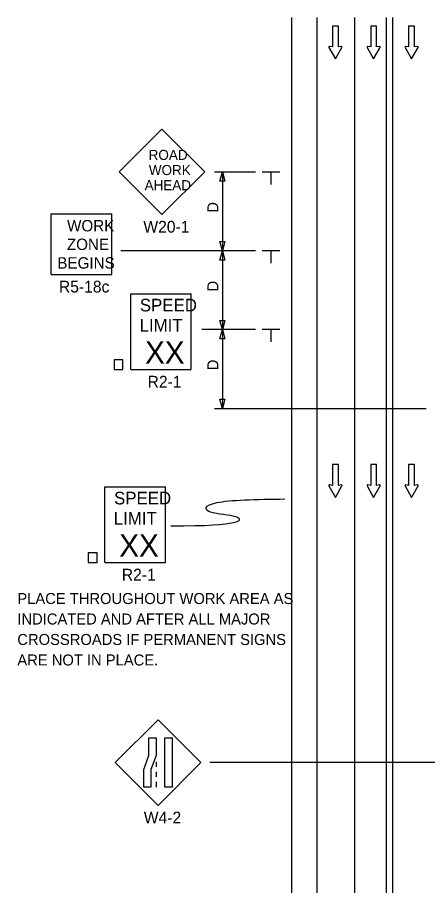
# Model space of a CAD drawing. Extents: x 16733 to 18475, y 7003 to 8205.
# Drawn here: x 16737 to 16998, y 7640 to 8191 of the extents above; entities that cross this region are included whole.
import ezdxf

# ---------------------------------------------------------------- set-up
doc = ezdxf.new("R2010")
doc.units = 0
for name, color, linetype in [('ALI_LEGAL_EX', 7, 'Continuous'), ('MT_SCRATCH_LEVEL_E', 7, 'Continuous'), ('PAVT_EDGE_EX', 7, 'Continuous'), ('TRAFFIC_SIGNS_PR', 7, 'Continuous'), ('TYPICAL_TEXT_DIMEN_PR', 7, 'Continuous')]:
    doc.layers.add(name, color=color, linetype=linetype)

msp = doc.modelspace()

# ---------------------------------------------------------------- linework, layer by layer
at = {"layer": 'ALI_LEGAL_EX'}
for p, q in [((16951.37, 8191.42), (16951.37, 7362.23)), ((16971.37, 8191.42), (16971.37, 7362.23)), ((16975.37, 8191.42), (16975.37, 7362.23))]:
    msp.add_line(p, q, dxfattribs=at)
for points in [[(16951.37, 8191.42), (16951.37, 8166.42)], [(16975.37, 8191.42), (16975.37, 8166.42)], [(16951.37, 8091.42), (16951.37, 8066.42)], [(16975.37, 8091.42), (16975.37, 8066.42)], [(16951.37, 7991.42), (16951.37, 7966.42)], [(16975.37, 7991.42), (16975.37, 7966.42)], [(16951.37, 7891.42), (16951.37, 7866.42)], [(16975.37, 7891.42), (16975.37, 7866.42)], [(16951.37, 7791.42), (16951.37, 7766.42)], [(16975.37, 7791.42), (16975.37, 7766.42)], [(16951.37, 7691.42), (16951.37, 7666.42)], [(16975.37, 7691.42), (16975.37, 7666.42)]]:
    msp.add_lwpolyline(points, dxfattribs=at)
at = {"layer": 'MT_SCRATCH_LEVEL_E'}
for p, q in [((16941.03, 8185.91), (16937.29, 8185.91)), ((16937.29, 8185.91), (16937.29, 8172.66)), ((16941.03, 8185.91), (16937.29, 8185.91)), ((16937.29, 8185.91), (16937.29, 8172.66)), ((16941.03, 8172.66), (16941.03, 8185.91)), ((16941.03, 8172.66), (16941.03, 8185.91)), ((16965.29, 8185.91), (16961.55, 8185.91)), ((16961.55, 8185.91), (16961.55, 8172.66)), ((16965.29, 8185.91), (16961.55, 8185.91)), ((16961.55, 8185.91), (16961.55, 8172.66)), ((16965.29, 8172.66), (16965.29, 8185.91)), ((16965.29, 8172.66), (16965.29, 8185.91)), ((16989.39, 8185.91), (16985.65, 8185.91)), ((16985.65, 8185.91), (16985.65, 8172.66)), ((16989.39, 8185.91), (16985.65, 8185.91)), ((16985.65, 8185.91), (16985.65, 8172.66)), ((16989.39, 8172.66), (16989.39, 8185.91)), ((16989.39, 8172.66), (16989.39, 8185.91)), ((16935.04, 8172.29), (16939.18, 8165.05)), ((16935.04, 8172.29), (16939.18, 8165.05)), ((16937.29, 8172.66), (16935.52, 8172.97)), ((16937.29, 8172.66), (16935.52, 8172.97)), ((16939.18, 8165.05), (16943.29, 8172.29)), ((16939.18, 8165.05), (16943.29, 8172.29)), ((16942.81, 8172.97), (16941.03, 8172.66)), ((16942.81, 8172.97), (16941.03, 8172.66)), ((16959.29, 8172.29), (16963.44, 8165.05)), ((16959.29, 8172.29), (16963.44, 8165.05)), ((16961.55, 8172.66), (16959.77, 8172.97)), ((16961.55, 8172.66), (16959.77, 8172.97)), ((16963.44, 8165.05), (16967.55, 8172.29)), ((16963.44, 8165.05), (16967.55, 8172.29)), ((16967.07, 8172.97), (16965.29, 8172.66)), ((16967.07, 8172.97), (16965.29, 8172.66)), ((16983.4, 8172.29), (16987.54, 8165.05)), ((16983.4, 8172.29), (16987.54, 8165.05)), ((16985.65, 8172.66), (16983.87, 8172.97)), ((16985.65, 8172.66), (16983.87, 8172.97)), ((16987.54, 8165.05), (16991.65, 8172.29)), ((16987.54, 8165.05), (16991.65, 8172.29)), ((16991.17, 8172.97), (16989.39, 8172.66)), ((16991.17, 8172.97), (16989.39, 8172.66)), ((16941.03, 7907.66), (16937.29, 7907.66)), ((16937.29, 7907.66), (16937.29, 7894.41)), ((16941.03, 7907.66), (16937.29, 7907.66)), ((16937.29, 7907.66), (16937.29, 7894.41)), ((16941.03, 7894.41), (16941.03, 7907.66)), ((16941.03, 7894.41), (16941.03, 7907.66)), ((16965.29, 7907.66), (16961.55, 7907.66)), ((16961.55, 7907.66), (16961.55, 7894.41)), ((16965.29, 7907.66), (16961.55, 7907.66)), ((16961.55, 7907.66), (16961.55, 7894.41)), ((16965.29, 7894.41), (16965.29, 7907.66)), ((16965.29, 7894.41), (16965.29, 7907.66)), ((16989.39, 7907.66), (16985.65, 7907.66)), ((16985.65, 7907.66), (16985.65, 7894.41)), ((16989.39, 7907.66), (16985.65, 7907.66)), ((16985.65, 7907.66), (16985.65, 7894.41)), ((16989.39, 7894.41), (16989.39, 7907.66)), ((16989.39, 7894.41), (16989.39, 7907.66)), ((16935.04, 7894.04), (16939.18, 7886.8)), ((16935.04, 7894.04), (16939.18, 7886.8)), ((16937.29, 7894.41), (16935.52, 7894.72)), ((16937.29, 7894.41), (16935.52, 7894.72)), ((16939.18, 7886.8), (16943.29, 7894.04)), ((16939.18, 7886.8), (16943.29, 7894.04)), ((16942.81, 7894.72), (16941.03, 7894.41)), ((16942.81, 7894.72), (16941.03, 7894.41)), ((16959.29, 7894.04), (16963.44, 7886.8)), ((16959.29, 7894.04), (16963.44, 7886.8)), ((16961.55, 7894.41), (16959.77, 7894.72)), ((16961.55, 7894.41), (16959.77, 7894.72)), ((16963.44, 7886.8), (16967.55, 7894.04)), ((16963.44, 7886.8), (16967.55, 7894.04)), ((16967.07, 7894.72), (16965.29, 7894.41)), ((16967.07, 7894.72), (16965.29, 7894.41)), ((16983.4, 7894.04), (16987.54, 7886.8)), ((16983.4, 7894.04), (16987.54, 7886.8)), ((16985.65, 7894.41), (16983.87, 7894.72)), ((16985.65, 7894.41), (16983.87, 7894.72)), ((16987.54, 7886.8), (16991.65, 7894.04)), ((16987.54, 7886.8), (16991.65, 7894.04)), ((16991.17, 7894.72), (16989.39, 7894.41)), ((16991.17, 7894.72), (16989.39, 7894.41))]:
    msp.add_line(p, q, dxfattribs=at)
for centre, start, end in [((16935.45, 8172.51), 80.0362, 209.7731), ((16935.45, 8172.51), 80.0362, 209.7731), ((16942.89, 8172.51), 330.4248, 99.9638), ((16942.89, 8172.51), 330.4248, 99.9638), ((16959.7, 8172.51), 80.0362, 209.7731), ((16959.7, 8172.51), 80.0362, 209.7731), ((16967.14, 8172.51), 330.4248, 99.9638), ((16967.14, 8172.51), 330.4248, 99.9638), ((16983.8, 8172.51), 80.0362, 209.7731), ((16983.8, 8172.51), 80.0362, 209.7731), ((16991.25, 8172.51), 330.4248, 99.9638), ((16991.25, 8172.51), 330.4248, 99.9638), ((16935.45, 7894.26), 80.0362, 209.7731), ((16935.45, 7894.26), 80.0362, 209.7731), ((16942.89, 7894.26), 330.4248, 99.9638), ((16942.89, 7894.26), 330.4248, 99.9638), ((16959.7, 7894.26), 80.0362, 209.7731), ((16959.7, 7894.26), 80.0362, 209.7731), ((16967.14, 7894.26), 330.4248, 99.9638), ((16967.14, 7894.26), 330.4248, 99.9638), ((16983.8, 7894.26), 80.0362, 209.7731), ((16983.8, 7894.26), 80.0362, 209.7731), ((16991.25, 7894.26), 330.4248, 99.9638), ((16991.25, 7894.26), 330.4248, 99.9638)]:
    msp.add_arc(centre, 0.463, start, end, dxfattribs=at)
at = {"layer": 'PAVT_EDGE_EX'}
for p, q in [((16911.37, 8191.42), (16911.37, 7362.23)), ((16927.37, 8191.42), (16927.37, 7362.23))]:
    msp.add_line(p, q, dxfattribs=at)
at = {"layer": 'TRAFFIC_SIGNS_PR'}
for p, q in [((16829.01, 8120.55), (16801.86, 8093.4)), ((16856.17, 8093.4), (16829.01, 8120.55)), ((16801.86, 8093.4), (16829.01, 8066.24)), ((16829.01, 8066.24), (16856.17, 8093.4)), ((16758.75, 8028.23), (16758.75, 8066.63)), ((16758.75, 8066.63), (16797.15, 8066.63)), ((16797.15, 8028.23), (16797.15, 8066.63)), ((16758.75, 8028.23), (16797.15, 8028.23)), ((16809.2, 8015.93), (16847.6, 8015.93)), ((16809.2, 7967.93), (16809.2, 8015.93)), ((16847.6, 7967.93), (16847.6, 8015.93)), ((16809.2, 7967.93), (16847.6, 7967.93)), ((16792.81, 7893.45), (16831.21, 7893.45)), ((16792.81, 7845.45), (16792.81, 7893.45)), ((16831.21, 7845.45), (16831.21, 7893.45)), ((16792.81, 7845.45), (16831.21, 7845.45)), ((16826.5, 7745.61), (16799.35, 7718.45)), ((16853.65, 7718.45), (16826.5, 7745.61)), ((16799.35, 7718.45), (16826.5, 7691.3)), ((16825.25, 7718.95), (16825.25, 7715.75)), ((16826.5, 7691.3), (16853.65, 7718.45)), ((16825.25, 7712.55), (16825.25, 7709.35)), ((16825.25, 7706.15), (16825.25, 7702.95))]:
    msp.add_line(p, q, dxfattribs=at)
for points in [[(16798.59, 7967.93), (16804.18, 7967.93), (16804.18, 7974.1), (16798.59, 7974.1)], [(16782.2, 7845.45), (16787.79, 7845.45), (16787.79, 7851.62), (16782.2, 7851.62)], [(16825.25, 7734.19), (16825.25, 7723.01), (16821.91, 7714.13), (16821.91, 7702.95), (16817.42, 7702.95), (16817.42, 7714.13), (16820.76, 7723.01), (16820.76, 7734.19)], [(16835.39, 7734.19), (16835.39, 7702.95), (16830.9, 7702.95), (16830.9, 7734.19)]]:
    msp.add_lwpolyline(points, close=True, dxfattribs=at)
at = {"layer": 'TYPICAL_TEXT_DIMEN_PR'}
for p, q in [((16888.37, 8093.23), (16862.37, 8093.23)), ((16865.8, 8087.37), (16867.37, 8093.23)), ((16867.37, 8093.23), (16867.37, 8043.23)), ((16867.37, 8093.23), (16868.94, 8087.37)), ((16903.87, 8093.23), (16892.62, 8093.23)), ((16898.24, 8093.23), (16898.24, 8085.45)), ((16867.37, 8087.37), (16865.8, 8087.37)), ((16868.94, 8087.37), (16867.37, 8087.37)), ((16867.37, 8043.23), (16865.8, 8049.09)), ((16865.8, 8049.09), (16867.37, 8049.09)), ((16867.37, 8049.09), (16868.94, 8049.09)), ((16868.94, 8049.09), (16867.37, 8043.23)), ((16888.37, 8043.23), (16802.89, 8043.23)), ((16865.8, 8037.37), (16867.37, 8043.23)), ((16867.37, 8043.23), (16867.37, 7993.23)), ((16867.37, 8043.23), (16868.94, 8037.37)), ((16903.87, 8043.23), (16892.62, 8043.23)), ((16898.24, 8043.23), (16898.24, 8035.45)), ((16867.37, 8037.37), (16865.8, 8037.37)), ((16868.94, 8037.37), (16867.37, 8037.37)), ((16867.37, 7993.23), (16865.8, 7999.09)), ((16865.8, 7999.09), (16867.37, 7999.09)), ((16867.37, 7999.09), (16868.94, 7999.09)), ((16868.94, 7999.09), (16867.37, 7993.23)), ((16888.37, 7993.23), (16854.31, 7993.23)), ((16865.8, 7987.37), (16867.37, 7993.23)), ((16867.37, 7993.23), (16867.37, 7943.23)), ((16867.37, 7993.23), (16868.94, 7987.37)), ((16903.87, 7993.23), (16892.62, 7993.23)), ((16898.24, 7993.23), (16898.24, 7985.45)), ((16867.37, 7987.37), (16865.8, 7987.37)), ((16868.94, 7987.37), (16867.37, 7987.37)), ((16867.37, 7943.23), (16865.8, 7949.09)), ((16865.8, 7949.09), (16867.37, 7949.09)), ((16867.37, 7949.09), (16868.94, 7949.09)), ((16868.94, 7949.09), (16867.37, 7943.23)), ((16862.37, 7943.23), (16996.75, 7943.23)), ((16859.36, 7718.7), (17007.56, 7718.7))]:
    msp.add_line(p, q, dxfattribs=at)
msp.add_open_spline([(16834.65, 7868.68), (16880.74, 7868.68), (16880.74, 7875.95), (16855.56, 7875.95), (16855.56, 7884.63), (16888.56, 7885.63), (16907.07, 7885.77)], degree=3, dxfattribs=at)

# ---------------------------------------------------------------- texts
at = {"layer": 'TRAFFIC_SIGNS_PR'}
for s, height, p in [('ROAD', 6.4, (16820.56, 8100.93)), ('WORK', 6.4, (16820.67, 8091.33)), ('AHEAD', 6.4, (16817.98, 8081.73)), ('WORK', 7.217, (16768.75, 8055.59)), ('W20-1', 7.44, (16817.18, 8054.81)), ('ZONE', 7.217, (16768.63, 8043.78)), ('BEGINS', 7.217, (16762.56, 8031.97)), ('R5-18c', 7.44, (16763.56, 8016.79)), ('SPEED', 8, (16814.96, 8004.79)), ('LIMIT', 8, (16814.8, 7991.99)), ('XX', 14.031, (16818.31, 7971.69)), ('R2-1', 7.44, (16819.87, 7956.49)), ('SPEED', 8, (16798.57, 7882.32)), ('LIMIT', 8, (16798.41, 7869.52)), ('XX', 14.031, (16801.92, 7849.21)), ('R2-1', 7.44, (16803.48, 7834.01)), ('PLACE THROUGHOUT WORK AREA AS', 7, (16737.17, 7819.08)), ('INDICATED AND AFTER ALL MAJOR', 7, (16737.17, 7806.08)), ('CROSSROADS IF PERMANENT SIGNS', 7, (16737.17, 7793.08)), ('ARE NOT IN PLACE.', 7, (16737.17, 7780.08)), ('W4-2', 7.44, (16817.46, 7679.86))]:
    msp.add_text(s, height=height, dxfattribs=at).set_placement(p)
at = {"layer": 'TYPICAL_TEXT_DIMEN_PR'}
for p in [(16864.81, 8067.45), (16864.81, 8017.45), (16864.81, 7967.45)]:
    msp.add_text('D', height=7, rotation=90, dxfattribs=at).set_placement(p)

doc.saveas('drawing.dxf')
